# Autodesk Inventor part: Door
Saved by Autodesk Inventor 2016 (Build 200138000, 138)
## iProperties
Created: 2016-03
Part Number: Door
Material: Generic
Document SubType Name: Modeling
Designer: bongo_000
Density: 1 g/cm^3
Appearance: Default
Author: bongo_000
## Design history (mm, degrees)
feature "Base1"
body "Solid1"
